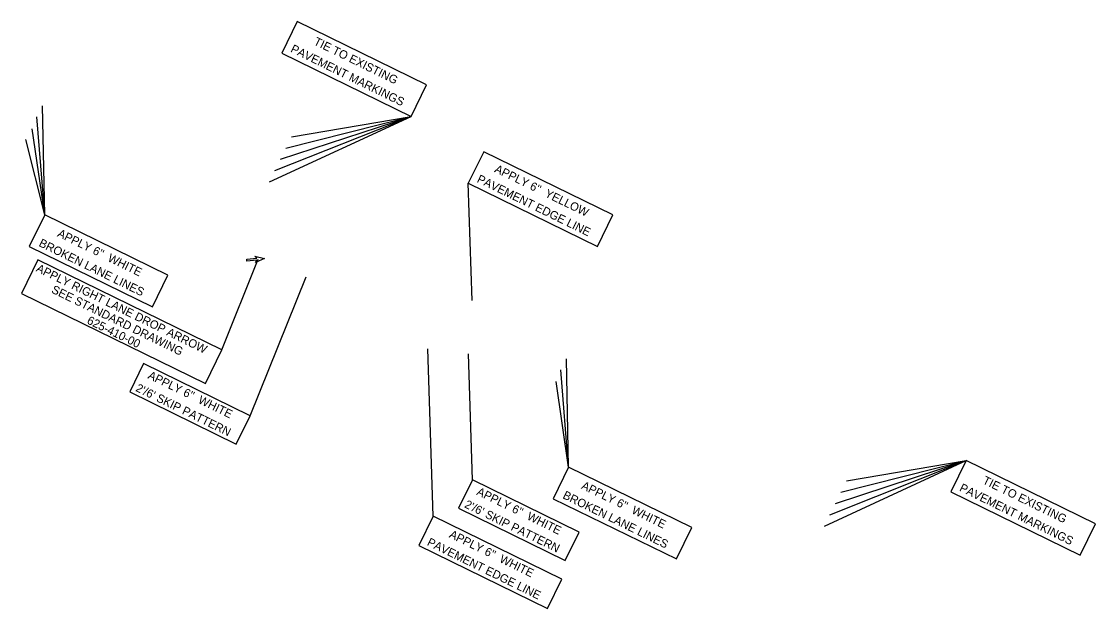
# Model space of a CAD drawing. Extents: x 1966013 to 1974896, y 789499 to 804826.
# Drawn here: x 1973871 to 1974896, y 793644 to 794204 of the extents above; entities that cross this region are included whole.
import ezdxf

# ---------------------------------------------------------------- set-up
doc = ezdxf.new("R2010")
doc.units = 0
doc.layers.add('RD_EX_H2O_BlueLn', color=7, linetype='Continuous')

msp = doc.modelspace()

# ---------------------------------------------------------------- linework, layer by layer
at = {"layer": 'RD_EX_H2O_BlueLn'}
for p, q in [((1973893.5, 794019.3), (1973891.3, 794123.5)), ((1973893.5, 794019.3), (1973885.9, 794112.8)), ((1974107.8, 794050.8), (1974243.2, 794113.4)), ((1974113.1, 794061.6), (1974243.2, 794113.4)), ((1974118.3, 794072.4), (1974243.2, 794113.4)), ((1974123.6, 794083.2), (1974243.2, 794113.4)), ((1974128.9, 794094), (1974243.2, 794113.4)), ((1973893.5, 794019.3), (1973881.5, 794101.6)), ((1973893.5, 794019.3), (1973875.5, 794091.2)), ((1974301.2, 793937.7), (1974297.6, 794049.6)), ((1974093.9, 793979.9), (1974103.3, 793977.9)), ((1974095.8, 793978), (1974093.9, 793979.9)), ((1974062.5, 793890.5), (1974097.3, 793977)), ((1974086.2, 793977), (1974095.8, 793978)), ((1974086.4, 793975.2), (1974086.2, 793977)), ((1974096, 793976.2), (1974086.4, 793975.2)), ((1974103.3, 793977.9), (1974094.6, 793974)), ((1974094.6, 793974), (1974096, 793976.2)), ((1974089.5, 793827.8), (1974142.8, 793960.4)), ((1974264.2, 793731.9), (1974259.1, 793891.5)), ((1974301.5, 793766.6), (1974297.7, 793886.7)), ((1974393.4, 793778.7), (1974391.2, 793882.2)), ((1974393.4, 793778.7), (1974385.8, 793871.5)), ((1974393.4, 793778.7), (1974381.5, 793860.3)), ((1974637.4, 793722.5), (1974772.7, 793785.1)), ((1974642.6, 793733.3), (1974772.7, 793785.1)), ((1974647.9, 793744.1), (1974772.7, 793785.1)), ((1974653.2, 793754.8), (1974772.7, 793785.1)), ((1974658.5, 793765.6), (1974772.7, 793785.1))]:
    msp.add_line(p, q, dxfattribs=at)
for points in [[(1974119.8, 794173.8), (1974243.2, 794113.4), (1974257.9, 794143.5), (1974134.5, 794203.9)], [(1974297.6, 794049.6), (1974421, 793989.2), (1974435.7, 794019.3), (1974312.4, 794079.7)], [(1973878.8, 793989.3), (1973996.3, 793931.7), (1974011, 793961.8), (1973893.5, 794019.3)], [(1973871.3, 793944.5), (1974046.9, 793858.6), (1974062.5, 793890.5), (1973886.9, 793976.4)], [(1973974.6, 793850.5), (1974076.3, 793800.7), (1974089.5, 793827.8), (1973987.8, 793877.6)], [(1974758, 793755), (1974881.4, 793694.6), (1974896.1, 793724.7), (1974772.7, 793785.1)], [(1974378.7, 793748.6), (1974496.2, 793691.1), (1974510.9, 793721.2), (1974393.4, 793778.7)], [(1974288.3, 793739.5), (1974390, 793689.7), (1974403.3, 793716.8), (1974301.5, 793766.6)], [(1974250.5, 793703.9), (1974373.3, 793643.8), (1974387, 793671.8), (1974264.2, 793731.9)]]:
    msp.add_lwpolyline(points, close=True, dxfattribs=at)

# ---------------------------------------------------------------- texts
for s, height, rotation, p in [('TIE TO EXISTING', 8, 333.9112, (1974149.5, 794182.2)), ('PAVEMENT MARKINGS', 8, 333.9112, (1974127.4, 794175.2)), ("APPLY 6''  YELLOW", 8, 333.9112, (1974322, 794060.6)), ('PAVEMENT EDGE LINE', 8, 333.9112, (1974305.2, 794051)), ("APPLY 6''  WHITE", 8, 333.9112, (1973904.9, 793999.1)), ('BROKEN LANE LINES', 8, 333.9112, (1973887.2, 793989.9)), ('APPLY RIGHT LANE DROP ARROW', 8, 333.9112, (1973884.6, 793965.8)), ('SEE STANDARD DRAWING', 8, 333.9112, (1973899.2, 793945.5)), ('625-410-00 ', 7.999, 333.9112, (1973933.1, 793916.1)), ("APPLY 6''  WHITE", 7.999, 333.9114, (1973991.2, 793863.7)), ("2'/6' SKIP PATTERN", 7.999, 333.9114, (1973979.6, 793851.6)), ("APPLY 6''  WHITE", 8, 333.9112, (1974404.8, 793758.5)), ('TIE TO EXISTING', 8, 333.9112, (1974787.7, 793763.4)), ("APPLY 6''  WHITE", 7.999, 333.9114, (1974304.9, 793752.7)), ('BROKEN LANE LINES', 8, 333.9112, (1974387.1, 793749.3)), ('PAVEMENT MARKINGS', 8, 333.9112, (1974765.6, 793756.4)), ("2'/6' SKIP PATTERN", 7.999, 333.9114, (1974293.3, 793740.6)), ("APPLY 6''  WHITE", 8, 333.9112, (1974278.7, 793712)), ('PAVEMENT EDGE LINE', 8, 333.9112, (1974257.6, 793704.5))]:
    msp.add_text(s, height=height, rotation=rotation, dxfattribs=at).set_placement(p)

doc.saveas('drawing.dxf')
